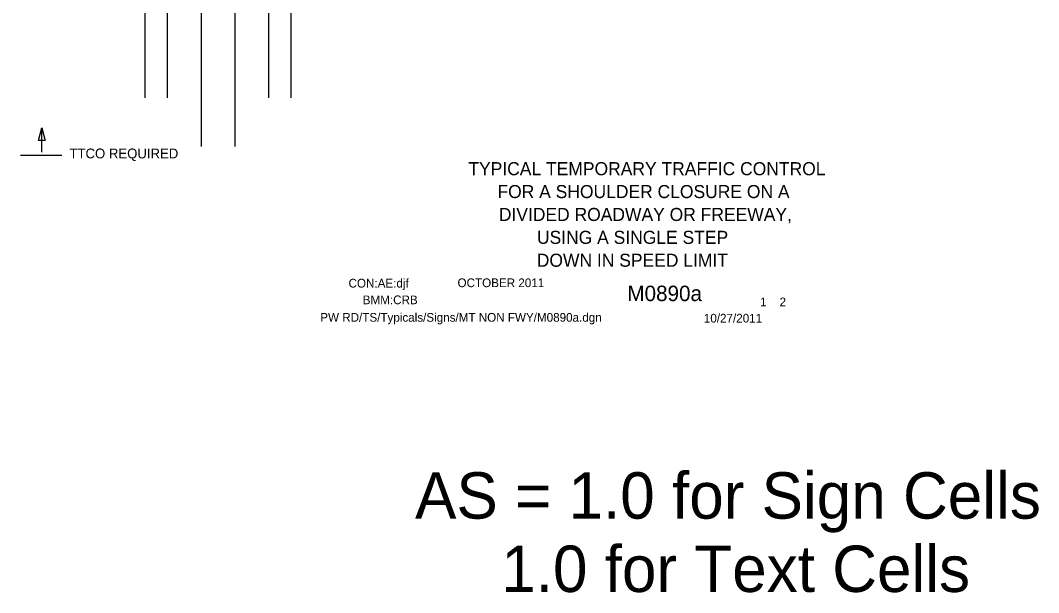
# Model space of a CAD drawing. Extents: x 16733 to 18471, y 7027 to 8225.
# Drawn here: x 16857 to 17582, y 7027 to 7435 of the extents above; entities that cross this region are included whole.
import ezdxf

# ---------------------------------------------------------------- set-up
doc = ezdxf.new("R2010")
doc.units = 0
for name, color, linetype in [('ALI_LEGAL_EX', 7, 'Continuous'), ('BORDER', 7, 'Continuous'), ('BORDER_SIGNAL_WO', 7, 'Continuous'), ('PAVT_EDGE_EX', 7, 'Continuous'), ('TYPICAL_TEXT_DIMEN_PR', 7, 'Continuous')]:
    doc.layers.add(name, color=color, linetype=linetype)

msp = doc.modelspace()

# ---------------------------------------------------------------- linework, layer by layer
at = {"layer": 'ALI_LEGAL_EX'}
for points in [[(16985.65, 7425.29), (16985.65, 7400.29)], [(17009.65, 7425.29), (17009.65, 7400.29)]]:
    msp.add_lwpolyline(points, dxfattribs=at)
at = {"layer": 'PAVT_EDGE_EX'}
for p, q in [((16985.65, 8211.96), (16985.65, 7344.79)), ((17009.65, 8211.96), (17009.65, 7344.79)), ((16985.65, 8097.28), (16985.65, 7344.79)), ((17009.65, 8097.28), (17009.65, 7344.79)), ((16945.65, 7942.5), (16945.65, 7379.34)), ((16961.65, 7942.41), (16961.65, 7379.34)), ((17033.65, 7942.16), (17033.65, 7379.34)), ((17049.65, 7942.41), (17049.65, 7379.34))]:
    msp.add_line(p, q, dxfattribs=at)
at = {"layer": 'TYPICAL_TEXT_DIMEN_PR'}
for p, q in [((16869.93, 7349.15), (16872.29, 7357.95)), ((16872.29, 7340.82), (16872.29, 7357.95)), ((16872.29, 7357.95), (16874.64, 7349.15)), ((16872.29, 7349.15), (16869.93, 7349.15)), ((16874.64, 7349.15), (16872.29, 7349.15)), ((16886.46, 7338.32), (16857.02, 7338.32))]:
    msp.add_line(p, q, dxfattribs=at)

# ---------------------------------------------------------------- texts
at = {"layer": 'BORDER'}
for s, p in [('TYPICAL TEMPORARY TRAFFIC CONTROL', (17176.01, 7324.31)), ('FOR A SHOULDER CLOSURE ON A', (17196.72, 7308.01)), ('DIVIDED ROADWAY OR FREEWAY,', (17197.71, 7291.71)), ('USING A SINGLE STEP', (17224.85, 7275.41)), ('DOWN IN SPEED LIMIT', (17224.72, 7259.11))]:
    msp.add_text(s, height=9.3, dxfattribs=at).set_placement(p)
at = {"layer": 'BORDER_SIGNAL_WO'}
for s, height, p in [('CON:AE:djf', 6.2, (17090.69, 7244.31)), ('    OCTOBER 2011    ', 6.2, (17159.08, 7244.59)), ('    M0890a   ', 11, (17272.86, 7234.63)), ('BMM:CRB   ', 6.2, (17100.81, 7232.42)), (' 1    2 ', 6.2, (17381.45, 7230.95)), ('PW RD/TS/Typicals/Signs/MT NON FWY/M0890a.dgn     ', 6.2, (17070.55, 7219.96)), ('10/27/2011    ', 6.2, (17343.69, 7219.38)), ('AS = 1.0 for Sign Cells', 33.0301, (17138.06, 7079.7)), ('     1.0 for Text Cells', 33.0301, (17138.06, 7027.47))]:
    msp.add_text(s, height=height, dxfattribs=at).set_placement(p)
at = {"layer": 'TYPICAL_TEXT_DIMEN_PR'}
msp.add_text('TTCO REQUIRED', height=7, dxfattribs=at).set_placement((16891.98, 7336.3))

doc.saveas('drawing.dxf')
